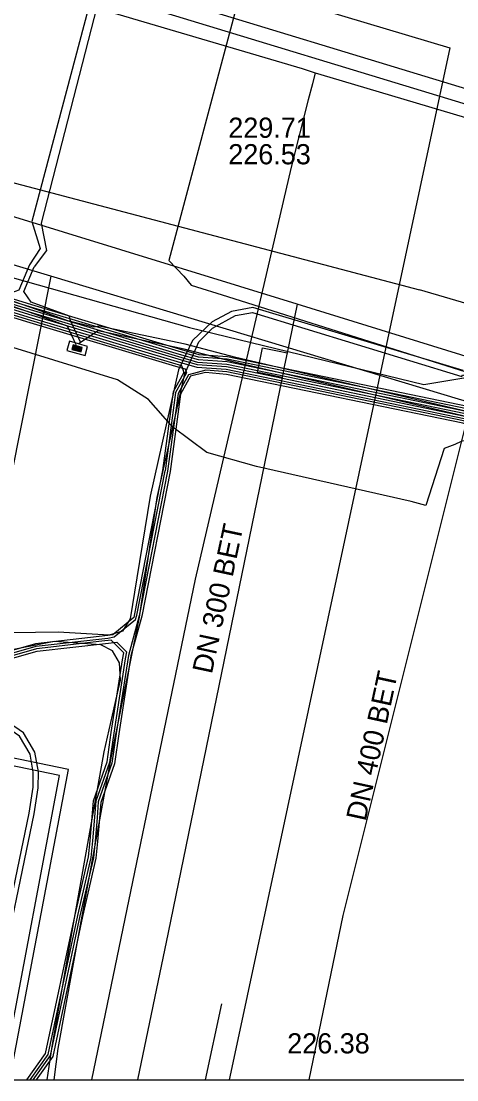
# Model space of a CAD drawing. Extents: x -599951 to -598963, y -1164095 to -1162939.
# Drawn here: x -599619.9 to -599602.64, y -1164094.69 to -1164052.74 of the extents above; entities that cross this region are included whole.
import ezdxf

# ---------------------------------------------------------------- set-up
doc = ezdxf.new("R2010")
doc.units = 0
for name, color, linetype in [('28', 7, 'Continuous'), ('Level 3', 7, 'Continuous'), ('Vrstva 1', 7, 'Continuous'), ('Vrstva 12', 7, 'Continuous'), ('Vrstva 13', 7, 'Continuous'), ('Vrstva 16', 7, 'Continuous'), ('Vrstva 19', 7, 'Continuous'), ('Vrstva 4', 7, 'Continuous'), ('Vrstva 42', 7, 'Continuous'), ('Vrstva 43', 7, 'Continuous'), ('Vrstva 44', 7, 'Continuous'), ('Vrstva 5', 7, 'Continuous'), ('Vrstva 53', 7, 'Continuous'), ('Vrstva 55', 7, 'Continuous'), ('Vrstva 58', 7, 'Continuous'), ('Vrstva 8', 7, 'Continuous')]:
    doc.layers.add(name, color=color, linetype=linetype)

# ---------------------------------------------------------------- blocks, each defined once
blk = doc.blocks.new('NN620')
at = {"layer": '28'}
for points in [[(0.752, 0.004), (-0.748, 0.004)], [(-0.748, 0.004), (-0.748, -0.746)], [(0.752, -0.746), (0.752, 0.004)], [(-0.748, -0.746), (0.752, -0.746)], [(0.368, -0.18), (-0.376, -0.18)], [(-0.376, -0.18), (-0.376, -0.558)], [(-0.376, -0.558), (0.368, -0.558)], [(0.321, -0.227), (-0.329, -0.227)], [(-0.329, -0.227), (-0.329, -0.51)], [(-0.329, -0.51), (0.321, -0.51)], [(0.274, -0.274), (-0.281, -0.274)], [(-0.281, -0.274), (-0.281, -0.463)], [(-0.281, -0.463), (0.274, -0.463)], [(0.227, -0.321), (-0.234, -0.321)], [(-0.234, -0.321), (-0.234, -0.416)], [(-0.234, -0.416), (0.227, -0.416)], [(-0.193, -0.369), (0.185, -0.369)], [(0.227, -0.416), (0.227, -0.321)], [(0.274, -0.463), (0.274, -0.274)], [(0.321, -0.51), (0.321, -0.227)], [(0.368, -0.558), (0.368, -0.18)]]:
    blk.add_lwpolyline(points, dxfattribs=at)

msp = doc.modelspace()

# ---------------------------------------------------------------- linework, layer by layer
at = {"layer": 'Level 3'}
msp.add_lwpolyline([(-599670.761, -1164034.874), (-599635.968, -1164045.241), (-599626.064, -1164047.883), (-599617.019, -1164050.914), (-599600, -1164056.104), (-599591.155, -1164058.802), (-599583.98, -1164060.87), (-599584.17, -1164061.41), (-599591.325, -1164059.378), (-599600, -1164056.732), (-599617.201, -1164051.486), (-599626.236, -1164048.457), (-599636.132, -1164045.819), (-599670.939, -1164035.446)], dxfattribs=at)
at = {"layer": 'Vrstva 1'}
for p, q in [((-599641.114, -1164053.622), (-599604.11, -1164063.39)), ((-599567.415, -1164074.246), (-599604.11, -1164063.39)), ((-599611.96, -1164091.68), (-599612.611, -1164094.695))]:
    msp.add_line(p, q, dxfattribs=at)
at = {"layer": 'Vrstva 12'}
for points in [[(-599611.95, -1164051.59), (-599611.61, -1164051.71), (-599611.4, -1164052.26), (-599614.05, -1164062.23), (-599613.46, -1164062.85)], [(-599603.87, -1164071.93), (-599604.45, -1164071.78), (-599610.58, -1164070.39), (-599612.54, -1164069.83), (-599613.89, -1164068.83), (-599614.85, -1164067.73), (-599616.08, -1164066.96), (-599647.82, -1164057.15), (-599655.82, -1164054.74)], [(-599613.46, -1164062.85), (-599613.16, -1164063.2), (-599611.72, -1164063.65), (-599602.03, -1164066.71), (-599599.57, -1164067.42), (-599595.65, -1164068.31), (-599580.24, -1164073.43), (-599577.04, -1164074.47), (-599566.64, -1164078.04), (-599562.59, -1164079.3), (-599551.43, -1164082.77), (-599546.18, -1164085.05), (-599534.35, -1164089.62), (-599520.153, -1164094.695)], [(-599512.817, -1164094.695), (-599549.011, -1164079.426), (-599551.753, -1164080.567), (-599560.66, -1164074.929), (-599578.175, -1164069.238), (-599581.79, -1164068.099), (-599587.439, -1164066.331), (-599595.493, -1164065.607), (-599599.144, -1164064.549), (-599601.105, -1164063.983), (-599607.16, -1164088.185), (-599608.496, -1164094.695)], [(-599596.47, -1164069.41), (-599600.24, -1164068.89), (-599602.46, -1164069.4), (-599602.72, -1164069.51), (-599603.14, -1164069.68), (-599603.87, -1164071.93)]]:
    msp.add_lwpolyline(points, dxfattribs=at)
at = {"layer": 'Vrstva 13'}
for p, q in [((-599608.77, -1164054.62), (-599608.25, -1164054.79)), ((-599608.25, -1164054.79), (-599608.36, -1164055.22)), ((-599608.25, -1164054.79), (-599607.67, -1164054.96))]:
    msp.add_line(p, q, dxfattribs=at)
for points in [[(-599708, -1164025.26), (-599702.264, -1164026.912), (-599699.155, -1164027.826), (-599681.16, -1164033.15), (-599677.61, -1164034.2), (-599645.3, -1164043.83), (-599608.77, -1164054.62)], [(-599608.36, -1164055.22), (-599608.526, -1164055.851), (-599609.2, -1164058.53)], [(-599607.67, -1164054.96), (-599590.92, -1164059.94), (-599589.853, -1164060.27), (-599573.8, -1164065.2), (-599570.07, -1164066.42), (-599549.24, -1164073.15), (-599540.472, -1164075.88), (-599508.435, -1164089.969), (-599502.44, -1164092.61), (-599497.429, -1164094.695)], [(-599609.2, -1164058.53), (-599613.006, -1164074.856), (-599617.11, -1164094.695)]]:
    msp.add_lwpolyline(points, dxfattribs=at)
at = {"layer": 'Vrstva 16'}
for points in [[(-599532.23, -1164094.695), (-599576.26, -1164075.92), (-599581.33, -1164074.29), (-599595.84, -1164069.64), (-599596.96, -1164069.28), (-599602.44, -1164067.76), (-599618.73, -1164062.85), (-599666.38, -1164048.5), (-599672.28, -1164046.86), (-599687.99, -1164042.5)], [(-599618.73, -1164062.85), (-599621.1, -1164074.75), (-599625.068, -1164094.695)]]:
    msp.add_lwpolyline(points, dxfattribs=at)
at = {"layer": 'Vrstva 19'}
for points in [[(-599517.408, -1164094.695), (-599537.5, -1164086.87), (-599571.84, -1164074.84), (-599589.93, -1164069.71), (-599590.38, -1164069.57), (-599590.89, -1164069.41), (-599601.93, -1164066.13), (-599608.97, -1164063.96), (-599646.01, -1164052.54), (-599646.71, -1164052.33), (-599646.97, -1164052.25), (-599649.244, -1164051.504), (-599665.68, -1164046.42), (-599687.59, -1164039.86)], [(-599608.97, -1164063.96), (-599609.16, -1164064.92)], [(-599609.16, -1164064.92), (-599609.36, -1164065.88), (-599609.46, -1164066.37)], [(-599609.46, -1164066.37), (-599609.56, -1164066.86), (-599610.05, -1164066.76), (-599610.54, -1164066.66), (-599610.34, -1164065.68), (-599609.75, -1164065.8), (-599609.36, -1164065.88)], [(-599609.56, -1164066.86), (-599614.07, -1164088.85), (-599615.291, -1164094.695)]]:
    msp.add_lwpolyline(points, dxfattribs=at)
at = {"layer": 'Vrstva 42'}
for points in [[(-599667, -1163993.46), (-599669.9, -1164004.29), (-599672.49, -1164011.1), (-599676.75, -1164026.4), (-599676.92, -1164027.5), (-599676.41, -1164028.19), (-599669.7, -1164030.95), (-599658.77, -1164034.16), (-599648.93, -1164037.44), (-599640.13, -1164039.85), (-599625.55, -1164044.94), (-599617.7, -1164047.09), (-599616.53, -1164049.22), (-599617.07, -1164051.6), (-599619.484, -1164060.682), (-599619.155, -1164061.753), (-599619.572, -1164062.391)], [(-599666.6, -1163993.43), (-599669.67, -1164004.37), (-599672.17, -1164011.18), (-599676.46, -1164026.39), (-599676.53, -1164027.48), (-599676.13, -1164027.87), (-599669.65, -1164030.47), (-599658.68, -1164033.66), (-599648.83, -1164037.1), (-599640.04, -1164039.44), (-599625.37, -1164044.54), (-599617.62, -1164046.76), (-599616.16, -1164049.44), (-599616.79, -1164051.7), (-599619.103, -1164060.744), (-599618.903, -1164061.834), (-599619.388, -1164062.469)], [(-599619.572, -1164062.391), (-599619.996, -1164063.403), (-599620.434, -1164063.552), (-599627.491, -1164061.289), (-599633.302, -1164059.547), (-599634.786, -1164059.717), (-599635.73, -1164060.66), (-599636.23, -1164062.34), (-599636.81, -1164065.03), (-599637.15, -1164066.29), (-599638.07, -1164069.27), (-599638.97, -1164073.33), (-599639.88, -1164075.85), (-599641.23, -1164078.6), (-599642.51, -1164080.28), (-599643.66, -1164081.19), (-599644.25, -1164081.48)], [(-599602.237, -1164068.213), (-599611.396, -1164066.063), (-599613.397, -1164065.543), (-599616.809, -1164064.822), (-599617.036, -1164064.869), (-599618.05, -1164064.62), (-599619.3, -1164064.16), (-599620.75, -1164063.66), (-599627.55, -1164061.48), (-599633.32, -1164059.75), (-599634.71, -1164059.91), (-599635.557, -1164060.781), (-599636.036, -1164062.39), (-599636.616, -1164065.077), (-599636.958, -1164066.346), (-599637.876, -1164069.321), (-599638.778, -1164073.386), (-599639.696, -1164075.928), (-599641.059, -1164078.706), (-599642.366, -1164080.421), (-599643.553, -1164081.36), (-599644.162, -1164081.659)], [(-599617.721, -1164065.572), (-599618.065, -1164064.829), (-599619.365, -1164064.349), (-599620.811, -1164063.85), (-599627.609, -1164061.671), (-599633.338, -1164059.953), (-599634.634, -1164060.103), (-599635.376, -1164060.874), (-599635.842, -1164062.439), (-599636.421, -1164065.124), (-599636.766, -1164066.401), (-599637.683, -1164069.372), (-599638.585, -1164073.442), (-599639.511, -1164076.007), (-599640.888, -1164078.811), (-599642.222, -1164080.562), (-599643.445, -1164081.53), (-599644.074, -1164081.839)], [(-599617.539, -1164065.488), (-599617.959, -1164064.578), (-599617.981, -1164064.432), (-599619.504, -1164063.874), (-599619.802, -1164063.455), (-599619.388, -1164062.469)], [(-599565.43, -1164079.839), (-599567.196, -1164079.669), (-599569.479, -1164079.126), (-599572.125, -1164078.144), (-599576.007, -1164076.713), (-599576.69, -1164077.29), (-599576.872, -1164076.585), (-599576.961, -1164076.241), (-599581.25, -1164074.885), (-599584.411, -1164073.875), (-599594.199, -1164070.686), (-599597.037, -1164069.906), (-599601.23, -1164068.704), (-599601.92, -1164069.53), (-599602.229, -1164068.421), (-599611.444, -1164066.257), (-599613.443, -1164065.737), (-599616.851, -1164065.018), (-599617.63, -1164065.53)], [(-599620.364, -1164094.695), (-599620.188, -1164093.84), (-599618.028, -1164082.395), (-599625.064, -1164080.947), (-599635.205, -1164078.822), (-599637.111, -1164076.901), (-599640.071, -1164076.089), (-599640.981, -1164077.825), (-599641.343, -1164079.008)], [(-599620.67, -1164094.695), (-599620.482, -1164093.782), (-599618.378, -1164082.629), (-599625.125, -1164081.241), (-599635.248, -1164079.099), (-599637.164, -1164077.094), (-599639.969, -1164076.325), (-599640.796, -1164077.901), (-599641.152, -1164079.066)], [(-599621.434, -1164094.695), (-599621.031, -1164092.736), (-599620.861, -1164091.236), (-599619.381, -1164084.157), (-599619.23, -1164083.118), (-599619.22, -1164082.492), (-599619.355, -1164081.715), (-599619.815, -1164080.941), (-599620.362, -1164080.554), (-599622.905, -1164080.2), (-599627.5, -1164080.37), (-599634.065, -1164078.793), (-599638.393, -1164077.641), (-599639.802, -1164077.519), (-599640.413, -1164077.602), (-599640.61, -1164077.977), (-599640.961, -1164079.125)], [(-599621.638, -1164094.695), (-599621.229, -1164092.704), (-599621.059, -1164091.204), (-599619.579, -1164084.123), (-599619.43, -1164083.102), (-599619.42, -1164082.508), (-599619.545, -1164081.785), (-599619.965, -1164081.079), (-599620.438, -1164080.746), (-599622.915, -1164080.4), (-599627.52, -1164080.57), (-599634.115, -1164078.987), (-599638.427, -1164077.839), (-599639.798, -1164077.721), (-599640.284, -1164077.788), (-599640.424, -1164078.054), (-599640.769, -1164079.183)]]:
    msp.add_lwpolyline(points, dxfattribs=at)
at = {"layer": 'Vrstva 44'}
for points in [[(-599713.076, -1164035.902), (-599703.955, -1164038.752), (-599695.016, -1164041.252), (-599688.692, -1164043.173), (-599677.704, -1164046.543), (-599672.728, -1164047.994), (-599667.14, -1164049.944), (-599657.488, -1164052.642), (-599649.966, -1164054.832), (-599642.274, -1164057.053), (-599633.284, -1164059.853), (-599627.565, -1164061.482), (-599619.491, -1164063.974), (-599613.646, -1164065.724), (-599612.857, -1164065.953), (-599611.723, -1164066.031), (-599602.21, -1164068), (-599596.912, -1164069.837), (-599596.588, -1164069.897), (-599596.29, -1164069.74), (-599595.75, -1164069.044), (-599595.695, -1164068.82), (-599595.236, -1164067.34)], [(-599713.16, -1164036.19), (-599704.04, -1164039.04), (-599695.1, -1164041.54), (-599688.78, -1164043.46), (-599677.79, -1164046.83), (-599672.82, -1164048.28), (-599667.23, -1164050.23), (-599657.57, -1164052.93), (-599650.05, -1164055.12), (-599642.36, -1164057.34), (-599633.37, -1164060.14), (-599627.65, -1164061.77), (-599619.58, -1164064.26), (-599613.67, -1164066.03), (-599612.91, -1164066.25)], [(-599657.652, -1164053.219), (-599650.134, -1164055.408), (-599642.446, -1164057.627), (-599633.456, -1164060.428), (-599627.735, -1164062.058), (-599619.669, -1164064.546), (-599614.974, -1164065.959), (-599613.547, -1164066.383), (-599613.453, -1164066.669), (-599613.877, -1164067.428), (-599614.299, -1164070.544), (-599615.411, -1164076.225), (-599615.441, -1164076.379), (-599616.265, -1164077.053), (-599616.461, -1164077.084), (-599619.33, -1164077.412), (-599624.926, -1164079.011), (-599627.855, -1164079.15)], [(-599657.597, -1164053.026), (-599650.078, -1164055.216), (-599642.389, -1164057.436), (-599633.399, -1164060.236), (-599627.678, -1164061.866), (-599619.609, -1164064.356), (-599613.698, -1164066.126), (-599612.928, -1164066.349), (-599611.764, -1164066.429), (-599602.317, -1164068.387), (-599597.039, -1164070.216), (-599596.349, -1164070.287), (-599595.132, -1164070.597), (-599594.278, -1164070.916), (-599584.55, -1164074.195), (-599581.301, -1164075.165), (-599576.114, -1164076.964), (-599572.226, -1164078.463), (-599569.659, -1164079.436), (-599567.285, -1164079.969), (-599563.799, -1164080.269)], [(-599657.543, -1164052.834), (-599650.022, -1164055.024), (-599642.331, -1164057.244), (-599633.341, -1164060.044), (-599627.622, -1164061.674), (-599619.551, -1164064.164), (-599613.642, -1164065.934), (-599612.892, -1164066.151), (-599611.736, -1164066.231), (-599602.263, -1164068.193), (-599596.981, -1164070.024), (-599596.262, -1164070.1), (-599595.065, -1164070.401), (-599594.222, -1164070.724), (-599584.49, -1164074.005), (-599581.239, -1164074.975), (-599576.046, -1164076.776), (-599572.154, -1164078.277), (-599569.601, -1164079.244), (-599567.255, -1164079.771), (-599563.761, -1164080.071)], [(-599602.39, -1164066.59), (-599610.72, -1164064.09), (-599611.56, -1164064.24), (-599612.33, -1164064.66), (-599613.11, -1164065.4), (-599613.67, -1164066.56), (-599614.79, -1164071.56), (-599615.315, -1164074.796), (-599615.58, -1164076.43), (-599615.88, -1164076.92), (-599616.42, -1164077.07), (-599618.44, -1164076.95), (-599621.13, -1164076.99)], [(-599618.59, -1164094.695), (-599618.44, -1164093.46), (-599617.57, -1164088.71), (-599616.32, -1164081.87), (-599615.21, -1164076.36), (-599614.51, -1164071.62), (-599613.41, -1164066.72), (-599612.86, -1164065.45), (-599612.32, -1164064.9), (-599611.41, -1164064.41), (-599610.74, -1164064.29), (-599602.44, -1164066.82), (-599602.41, -1164066.76), (-599596.88, -1164068.74), (-599589.54, -1164071.01), (-599582.61, -1164073.2), (-599576.16, -1164075.41), (-599569.51, -1164077.47), (-599564.88, -1164079.03)], [(-599612.91, -1164066.25), (-599611.75, -1164066.33), (-599602.29, -1164068.29), (-599597.01, -1164070.12), (-599594.25, -1164070.82)], [(-599563.837, -1164080.466), (-599567.316, -1164080.167), (-599569.716, -1164079.628), (-599572.297, -1164078.65), (-599576.183, -1164077.152), (-599581.362, -1164075.356), (-599584.611, -1164074.386), (-599594.335, -1164071.108), (-599595.198, -1164070.786), (-599596.483, -1164070.459), (-599597.096, -1164070.408), (-599602.37, -1164068.58), (-599611.745, -1164066.637), (-599612.583, -1164066.566), (-599613.275, -1164066.762), (-599613.683, -1164067.492), (-599614.101, -1164070.576), (-599615.223, -1164076.303), (-599615.651, -1164077.875), (-599616.131, -1164080.965), (-599616.302, -1164082.144), (-599616.846, -1164083.683)], [(-599619.677, -1164094.695), (-599618.933, -1164093.649), (-599617.768, -1164088.158), (-599617.239, -1164085.863), (-599617.17, -1164085.221), (-599617.04, -1164083.642), (-599616.498, -1164082.096), (-599616.329, -1164080.935), (-599615.881, -1164078.049), (-599615.839, -1164077.77), (-599616.33, -1164077.272), (-599616.706, -1164077.313), (-599619.29, -1164077.608), (-599624.894, -1164079.209)], [(-599618.876, -1164094.695), (-599618.67, -1164093.37), (-599617.83, -1164088.51), (-599616.61, -1164081.7), (-599616.088, -1164079.369), (-599615.97, -1164078.85), (-599616.01, -1164078.17), (-599616.28, -1164077.69), (-599616.75, -1164077.46), (-599618.6, -1164077.33), (-599620.72, -1164077.74)], [(-599616.846, -1164083.683), (-599616.894, -1164084.316), (-599616.97, -1164085.239), (-599617.041, -1164085.897), (-599617.572, -1164088.202), (-599618.746, -1164093.731), (-599619.433, -1164094.695)]]:
    msp.add_lwpolyline(points, dxfattribs=at)
at = {"layer": 'Vrstva 5'}
for p, q in [((-599633.99, -1164044.5), (-599602.92, -1164053.79)), ((-599602.92, -1164053.79), (-599611.36, -1164093.28)), ((-599611.36, -1164093.28), (-599611.661, -1164094.695))]:
    msp.add_line(p, q, dxfattribs=at)
at = {"layer": 'Vrstva 53'}
msp.add_lwpolyline([(-599951.125, -1164094.695), (-598963.215, -1164094.695), (-598963.215, -1162939.4), (-599951.125, -1162939.4)], close=True, dxfattribs=at)
at = {"layer": 'Vrstva 55'}
msp.add_lwpolyline([(-599730.225, -1164030.406), (-599699.561, -1164039.03), (-599699.101, -1164037.918), (-599699.561, -1164039.03), (-599667.715, -1164049.284), (-599667.086, -1164049.415), (-599666.671, -1164048.038), (-599667.086, -1164049.415), (-599641.77, -1164056.83), (-599641.359, -1164055.754), (-599641.77, -1164056.83), (-599613.23, -1164064.88), (-599603.95, -1164067.14), (-599599.17, -1164066.34), (-599581.67, -1164071.86), (-599567.7, -1164076.51), (-599564.49, -1164079.74), (-599552.92, -1164083.71), (-599548.31, -1164083.01), (-599521.3, -1164092.7), (-599516.137, -1164094.695)], dxfattribs=at)
at = {"layer": 'Vrstva 58'}
for points in [[(-599734.065, -1164030.453), (-599733.861, -1164030.517), (-599730.018, -1164031.722), (-599720.861, -1164034.504), (-599713.272, -1164036.574), (-599704.154, -1164039.424), (-599695.212, -1164041.924), (-599688.897, -1164043.843), (-599677.905, -1164047.213), (-599672.942, -1164048.661), (-599667.35, -1164050.612), (-599657.68, -1164053.315), (-599650.161, -1164055.504), (-599642.475, -1164057.723), (-599633.484, -1164060.523), (-599627.764, -1164062.153), (-599619.696, -1164064.643), (-599613.783, -1164066.414), (-599613.396, -1164066.523), (-599613.344, -1164066.681), (-599613.556, -1164067.06), (-599613.78, -1164067.46), (-599614.2, -1164070.56)], [(-599595.341, -1164067.328), (-599595.8, -1164068.805), (-599595.92, -1164069.426), (-599596.224, -1164069.818), (-599596.541, -1164069.986), (-599596.945, -1164069.931), (-599602.237, -1164068.097), (-599611.736, -1164066.13), (-599612.875, -1164066.052), (-599613.674, -1164065.82), (-599619.522, -1164064.069), (-599627.593, -1164061.578), (-599633.313, -1164059.948), (-599642.303, -1164057.148), (-599649.994, -1164054.928), (-599657.515, -1164052.738), (-599667.17, -1164050.039), (-599672.759, -1164048.089), (-599677.733, -1164046.638), (-599688.722, -1164043.269), (-599695.044, -1164041.348), (-599703.983, -1164038.848), (-599713.104, -1164035.998)], [(-599657.625, -1164053.122), (-599650.106, -1164055.312), (-599642.417, -1164057.532), (-599633.427, -1164060.332), (-599627.707, -1164061.962), (-599619.638, -1164064.451), (-599613.726, -1164066.222), (-599612.945, -1164066.448), (-599611.777, -1164066.529), (-599602.343, -1164068.483), (-599597.067, -1164070.312), (-599596.407, -1164070.375), (-599595.151, -1164070.695), (-599594.307, -1164071.012), (-599584.581, -1164074.291), (-599581.331, -1164075.26), (-599576.149, -1164077.058), (-599572.261, -1164078.557), (-599569.688, -1164079.532), (-599567.301, -1164080.068), (-599563.818, -1164080.367)], [(-599657.57, -1164052.93), (-599650.05, -1164055.12), (-599642.36, -1164057.34), (-599633.37, -1164060.14), (-599627.65, -1164061.77), (-599619.58, -1164064.26), (-599613.67, -1164066.03), (-599612.91, -1164066.25), (-599611.75, -1164066.33), (-599602.29, -1164068.29), (-599597.01, -1164070.12), (-599596.288, -1164070.199), (-599595.11, -1164070.499), (-599594.25, -1164070.82), (-599584.52, -1164074.1), (-599581.27, -1164075.07), (-599576.08, -1164076.87), (-599572.19, -1164078.37), (-599569.63, -1164079.34), (-599567.27, -1164079.87), (-599563.78, -1164080.17)], [(-599563.855, -1164080.565), (-599567.331, -1164080.266), (-599569.745, -1164079.724), (-599572.333, -1164078.744), (-599576.218, -1164077.246), (-599581.393, -1164075.451), (-599584.641, -1164074.481), (-599594.363, -1164071.204), (-599595.228, -1164070.882), (-599596.591, -1164070.535), (-599597.125, -1164070.504), (-599602.397, -1164068.676), (-599611.759, -1164066.737), (-599612.591, -1164066.665), (-599613.188, -1164066.811), (-599613.587, -1164067.525), (-599614.003, -1164070.593)], [(-599649.31, -1164080.34), (-599652.18, -1164079.57), (-599652.37, -1164078.53), (-599652.21, -1164076.86), (-599651.2, -1164074.07), (-599650.77, -1164073.45), (-599649.86, -1164073.52), (-599641.47, -1164075.58), (-599639.86, -1164076.03), (-599638.29, -1164076.4), (-599629.66, -1164079.13), (-599627.856, -1164079.25), (-599624.91, -1164079.11), (-599619.31, -1164077.51), (-599616.468, -1164077.186), (-599616.211, -1164077.144), (-599615.367, -1164076.453), (-599615.32, -1164076.28), (-599614.2, -1164070.56)], [(-599614.003, -1164070.593), (-599615.125, -1164076.326), (-599615.553, -1164077.896), (-599616.032, -1164080.98), (-599616.205, -1164082.168), (-599616.747, -1164083.704), (-599616.795, -1164084.324), (-599616.871, -1164085.249), (-599616.942, -1164085.913), (-599617.475, -1164088.223), (-599618.653, -1164093.772), (-599619.31, -1164094.695)], [(-599624.877, -1164079.309), (-599619.271, -1164077.707), (-599616.446, -1164077.384), (-599616.116, -1164077.349), (-599615.731, -1164077.735), (-599615.774, -1164078.013), (-599616.23, -1164080.95), (-599616.4, -1164082.12), (-599616.94, -1164083.65), (-599617.07, -1164085.23), (-599617.14, -1164085.88), (-599617.67, -1164088.18), (-599618.84, -1164093.69), (-599619.555, -1164094.695)]]:
    msp.add_lwpolyline(points, dxfattribs=at)

# ---------------------------------------------------------------- block references
at = {"layer": 'Vrstva 43', "xscale": 0.5, "yscale": 0.5000000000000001, "rotation": -16.000000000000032}
msp.add_blockref('NN620', (-599617.63, -1164065.53), dxfattribs=at)

# ---------------------------------------------------------------- texts
at = {"layer": 'Vrstva 4'}
msp.add_text('DN 400 BET', height=0.8, rotation=77.7477, dxfattribs=at).set_placement((-599606.25, -1164084.476))
at = {"layer": 'Vrstva 8'}
for s, p in [('229.71', (-599611.695, -1164057.362)), ('226.53', (-599611.695, -1164058.412)), ('226.38', (-599609.359, -1164093.648))]:
    msp.add_text(s, height=0.8, dxfattribs=at).set_placement(p)
msp.add_text('DN 300 BET', height=0.8, rotation=77.936, dxfattribs=at).set_placement((-599612.345, -1164078.639))

doc.saveas('drawing.dxf')
